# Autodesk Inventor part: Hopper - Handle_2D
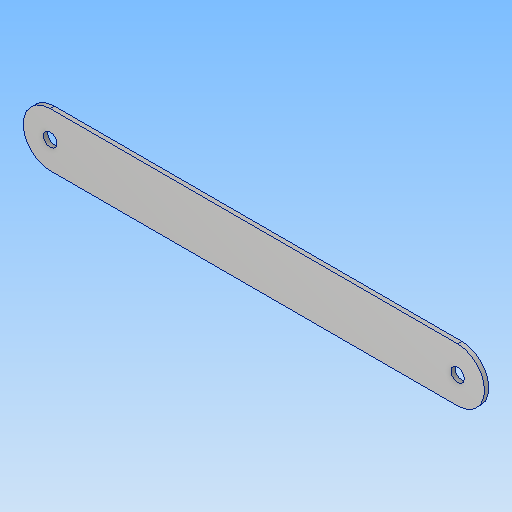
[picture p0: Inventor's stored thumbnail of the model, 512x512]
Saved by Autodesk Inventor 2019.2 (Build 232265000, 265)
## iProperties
Created: 2019-02
Part Number: Hopper - Handle_2D
Material: Aluminum 6061
Document SubType Name: Modeling
Designer: User
Density: 2.7 g/cm^3
Appearance: Aluminum - Flat
Author: User
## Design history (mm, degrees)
sketch "Hopper - Handle sketch"
  geometry: L1 (136.191, -20)-(-15.416, -20); L2 (-15.416, 0)-(136.191, 0); C1 r 2.5 at (136.191, -10); C2 r 2.5 at (-15.416, -10); A1 r 10 centre (136.191, -10) between (136.191, -20) and (136.191, 0); A2 r 10 centre (-15.416, -10) between (-15.416, 0) and (-15.416, -20)
  constraints: 4 centre point, 4 end point, 4 point on circle
extrude "Hopper - Handle extrude" new body sketch "Hopper - Handle sketch" stored distance "d0" = 1.5875; taper "d1" = 0 deg
node "Hopper - Handle"
